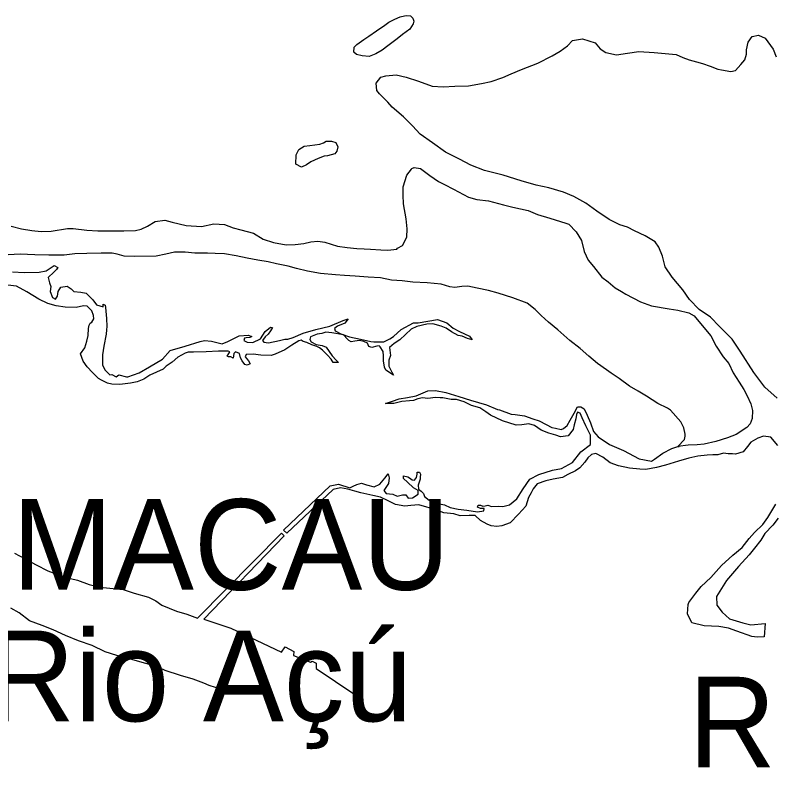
# Model space of a CAD drawing. Extents: x 662444 to 1640468, y 7452018 to 9606170.
# Drawn here: x 1427744 to 1433490, y 9427571 to 9433484 of the extents above; entities that cross this region are included whole.
import ezdxf

# ---------------------------------------------------------------- set-up
doc = ezdxf.new("R2010")
doc.units = 0
doc.layers.add('Level 1', color=7, linetype='Continuous')
doc.layers.add('Level 3', color=7, linetype='Continuous')

msp = doc.modelspace()

# ---------------------------------------------------------------- linework, layer by layer
at = {"layer": 'Level 1'}
for points in [[(1430678.3, 9433341.9), (1430636.3, 9433307.8), (1430565.1, 9433254), (1430523.2, 9433222.1), (1430475.8, 9433194.8), (1430425.1, 9433174.2), (1430372.5, 9433180.5), (1430328.9, 9433188.9), (1430307.9, 9433208.2), (1430311.7, 9433245), (1430332.2, 9433265.9), (1430385.3, 9433303.2), (1430421.5, 9433328.5), (1430481.4, 9433370.1), (1430542.4, 9433410.7), (1430574.1, 9433434.9), (1430619.2, 9433456.6), (1430659.8, 9433474), (1430692.4, 9433482.5), (1430710.4, 9433484.5), (1430738.4, 9433483), (1430756.1, 9433466), (1430762.5, 9433441.4), (1430758.8, 9433421.3), (1430732.6, 9433382.5), (1430678.3, 9433341.9)], [(1433519.7, 9430583.9), (1433425.5, 9430667.8), (1433340.7, 9430778.4), (1433238.6, 9430940.7), (1433177, 9431030.9), (1433081.9, 9431126), (1433013.4, 9431197.3), (1432927.9, 9431255.4), (1432852.7, 9431331.3), (1432804.3, 9431404.5), (1432722.7, 9431501.7), (1432668.8, 9431580.6), (1432648.6, 9431660.2), (1432621.5, 9431729.8), (1432592.8, 9431768.2), (1432518.4, 9431815), (1432437.1, 9431852.9), (1432382.5, 9431880.5), (1432325.6, 9431899.1), (1432245.5, 9431939.2), (1432151, 9432000.8), (1432067.8, 9432063.4), (1431977.7, 9432111.5), (1431897.4, 9432144.9), (1431788, 9432177.6), (1431690.8, 9432197.9), (1431577, 9432230.7), (1431442, 9432273.8), (1431299, 9432310.3), (1431196.4, 9432349.6), (1431108.5, 9432396.6), (1431003.9, 9432449.3), (1430904, 9432519.9), (1430810.7, 9432585.9), (1430753.3, 9432649.3), (1430685.8, 9432717.2), (1430598.2, 9432789.8), (1430566.2, 9432827.1), (1430502.1, 9432891.6), (1430483.4, 9432916.5), (1430478.5, 9432972.4), (1430513.8, 9433017.7), (1430552, 9433027.3), (1430628.3, 9433034.1), (1430706.5, 9433018.6), (1430798, 9432987.2), (1430902.8, 9432949), (1430984.6, 9432943.5), (1431074.3, 9432950.1), (1431177.4, 9432951), (1431276.2, 9432969.8), (1431349.3, 9432985.6), (1431439.3, 9433015.8), (1431502.4, 9433044), (1431579, 9433075.4), (1431704, 9433124.1), (1431811.2, 9433179.7), (1431872.2, 9433215.7), (1431929.8, 9433256.3), (1431967.3, 9433296.1), (1432042.6, 9433308.5), (1432138.5, 9433277.1), (1432177.2, 9433233), (1432220.5, 9433204.5), (1432299.8, 9433187.8), (1432384, 9433199), (1432470.5, 9433212.4), (1432585.8, 9433205.3), (1432753.7, 9433188.6), (1432802.7, 9433165.6), (1432851.7, 9433148.2), (1432907.6, 9433134.1), (1432951.1, 9433122.3), (1433010.2, 9433101.4), (1433068.2, 9433079.5), (1433096.2, 9433073.5), (1433167.7, 9433061.4), (1433202.5, 9433067.6), (1433243.5, 9433114), (1433274.2, 9433148.3), (1433284.9, 9433192.8), (1433285.3, 9433225.3), (1433299.5, 9433283.2), (1433328, 9433325.3), (1433376.4, 9433335.8), (1433427.6, 9433313.9), (1433487, 9433230.4), (1433510.9, 9433172)], [(1430108.3, 9432421.9), (1430083.6, 9432417.7), (1430038.6, 9432401.6), (1429982.2, 9432376.6), (1429948.3, 9432353.6), (1429911.1, 9432336.2), (1429868.8, 9432358), (1429872, 9432428.3), (1429891.5, 9432468.3), (1429932.2, 9432493.5), (1429976, 9432500.7), (1430050, 9432508.7), (1430078.2, 9432520.6), (1430099.6, 9432531.5), (1430138.9, 9432532.1), (1430171.2, 9432521.6), (1430187.6, 9432490.1), (1430180.5, 9432456.7), (1430163.4, 9432436.8), (1430108.3, 9432421.9)], [(1427710.4, 9431887.7), (1427788.6, 9431868.8), (1427865.7, 9431854.4), (1427937.3, 9431846.8), (1428013.5, 9431849.1), (1428135.9, 9431869.9), (1428180.7, 9431870.4), (1428282.5, 9431856.8), (1428366.5, 9431851.2), (1428470.7, 9431852.1), (1428563.7, 9431852), (1428653.3, 9431855.3), (1428694.9, 9431866), (1428743.4, 9431886.6), (1428802.1, 9431922.7), (1428876.2, 9431932.9), (1428932, 9431918.7), (1429037, 9431892.8), (1429152.3, 9431884.6), (1429246.7, 9431904.6), (1429327.3, 9431901.3), (1429394.2, 9431875.9), (1429452.2, 9431859.5), (1429548.3, 9431834.7), (1429620.5, 9431790.2), (1429699.7, 9431763.5), (1429795.9, 9431746.6), (1429863.1, 9431748), (1429929.3, 9431757.2), (1429983.3, 9431769.9), (1430036, 9431774.8), (1430088.6, 9431767.4), (1430183.4, 9431734.9), (1430257.2, 9431727.2), (1430330, 9431719.5), (1430387.1, 9431715.4), (1430434.1, 9431712.6), (1430513.6, 9431709.3), (1430566.2, 9431706.4), (1430635.7, 9431712.2), (1430640.3, 9431720), (1430676.5, 9431741.8), (1430709.8, 9431804), (1430712.8, 9431867.6), (1430706, 9431942.6), (1430686.2, 9432056.8), (1430682.5, 9432122.8), (1430683.4, 9432186.5), (1430711.4, 9432275.5), (1430746.7, 9432319.7), (1430749, 9432324.2), (1430764.8, 9432332.9), (1430814, 9432324.4), (1430883.9, 9432272.1), (1430950.6, 9432227.7)], [(1430950.6, 9432227.7), (1430995.1, 9432202.5), (1431064.1, 9432168.1), (1431178.7, 9432108.5), (1431241.2, 9432090.9), (1431330.7, 9432079.7), (1431443.5, 9432050.3), (1431515, 9432032.6), (1431631.2, 9432007.6), (1431701.4, 9431976.5), (1431794, 9431948.5), (1431916.8, 9431910), (1431939.1, 9431903), (1431993.2, 9431845.3), (1432035, 9431780), (1432055.2, 9431695.9), (1432084.6, 9431630.7), (1432126.5, 9431582.1), (1432189.3, 9431500.8), (1432235.9, 9431464.5), (1432291.3, 9431419), (1432336.9, 9431391.6), (1432371.4, 9431371.1), (1432482.7, 9431313.7), (1432566.3, 9431284.7), (1432700.5, 9431260.6), (1432766.4, 9431249.7), (1432849.1, 9431229.6), (1432890.3, 9431206.7), (1432949.8, 9431135.5), (1433016, 9431055.3), (1433055.3, 9430977.7), (1433108.1, 9430897.7), (1433151.1, 9430846.8), (1433184.9, 9430776), (1433231, 9430705), (1433266.2, 9430648.7), (1433290.2, 9430602.5), (1433319.6, 9430540.7), (1433331.3, 9430489.1), (1433328.3, 9430430), (1433313.2, 9430388.8), (1433288.2, 9430362.3), (1433207.9, 9430307.5), (1433141.5, 9430282.7), (1433052.6, 9430254.8), (1432966, 9430234.7), (1432911.1, 9430228.7), (1432844.9, 9430226.2), (1432765.2, 9430217.2), (1432774.2, 9430216)], [(1431622, 9431303.8), (1431513.9, 9431344.3), (1431402.3, 9431379.3), (1431329.7, 9431400.3), (1431244.8, 9431418.2), (1431172.1, 9431432.6), (1431126.2, 9431430.9), (1431074.5, 9431422.6), (1431035.4, 9431427.6), (1430969.6, 9431448.6), (1430865.5, 9431457.8), (1430755.8, 9431463.7), (1430675.2, 9431473.7), (1430593.5, 9431478.1), (1430509.7, 9431494.8), (1430417.9, 9431501.6), (1430319.3, 9431507.4), (1430238.8, 9431512.9), (1430168.2, 9431519.4), (1430056.3, 9431529.8), (1429957.9, 9431545.6), (1429874.2, 9431565.7), (1429809.4, 9431584.4), (1429722.3, 9431601.2), (1429658.6, 9431617.7), (1429579.2, 9431628.8), (1429498.8, 9431645.4), (1429416.1, 9431662.2), (1429327.8, 9431677.8), (1429257.2, 9431681), (1429197.8, 9431681.8), (1429103.7, 9431683), (1429028.8, 9431690.7), (1428948.1, 9431689.5), (1428881.8, 9431675.8), (1428809.9, 9431661.1), (1428645.2, 9431656.6), (1428566.8, 9431660.9), (1428514.3, 9431676.1), (1428476.3, 9431683.3), (1428460.6, 9431683.5), (1428391.2, 9431682.2), (1428284.7, 9431680.2), (1428193.9, 9431679.2), (1428110.9, 9431666.9), (1427994.4, 9431668.4), (1427889.1, 9431670.9), (1427779.3, 9431675.6), (1427686.3, 9431671.3)], [(1427720.5, 9431542.3), (1427807.8, 9431535.6), (1427921, 9431538.6), (1427974.9, 9431550.2), (1428034.8, 9431589.6), (1428063.7, 9431573.6), (1428053.4, 9431558.1), (1428034.1, 9431539.4), (1427989.9, 9431497.5), (1427999.5, 9431457.1), (1428010.3, 9431430.2), (1428005.4, 9431393.4), (1428023.8, 9431346.2), (1428046, 9431334.7), (1428060.9, 9431358), (1428067, 9431392.6), (1428086.4, 9431424.7), (1428133.6, 9431433.1), (1428165.8, 9431413.6), (1428184.6, 9431393.3), (1428238.3, 9431388.1), (1428279.7, 9431379.7), (1428328.3, 9431330), (1428358.1, 9431291.6), (1428407.1, 9431275.3), (1428408.5, 9431296.5), (1428423, 9431288.5), (1428425, 9431270.6), (1428431.8, 9431187.8), (1428434.4, 9431127.5), (1428431.8, 9431101.8), (1428429.1, 9431068.3), (1428413.4, 9430978), (1428402.4, 9430912.2), (1428401.4, 9430835.1), (1428420, 9430799.2)], [(1430259.3, 9431029.9), (1430229.5, 9431064.9), (1430142.3, 9431079.5), (1430096.5, 9431084.6), (1430066.1, 9431072.7), (1430030.2, 9431069.8), (1429979.5, 9431049.2), (1429973.6, 9431028.1), (1429984.6, 9431011.2), (1430022.4, 9430990.6), (1430067.1, 9430983.3), (1430099.5, 9430970.5), (1430120.3, 9430937.9), (1430143.4, 9430904.1), (1430173.3, 9430872.4), (1430190.9, 9430853.2), (1430150.6, 9430853.7), (1430136.4, 9430879.6), (1430108.8, 9430910.1), (1430071.2, 9430947.5), (1430047.8, 9430964.5), (1430026.7, 9430976), (1429988.8, 9430987.6), (1429953.1, 9431004.9), (1429924.1, 9431014.2), (1429909.7, 9431024.4), (1429890.6, 9431018), (1429838.6, 9430986.2), (1429784.4, 9430950.1), (1429712.2, 9430917.5), (1429681.8, 9430906.7), (1429602.3, 9430908.9), (1429544.1, 9430916.3), (1429491.5, 9430915.9), (1429485.6, 9430895.9), (1429509.9, 9430865.4), (1429523, 9430842.9), (1429499.4, 9430833.1), (1429482.6, 9430837.8), (1429462.8, 9430866), (1429448.5, 9430888.5), (1429442.3, 9430923.3), (1429412.2, 9430933.7), (1429398.6, 9430922.7), (1429392.5, 9430885.9), (1429374.7, 9430897.3), (1429357.9, 9430896.4), (1429349, 9430902.1), (1429359.3, 9430921), (1429368.5, 9430935.4), (1429355.1, 9430941.1), (1429329.4, 9430940.4), (1429283.4, 9430939.9), (1429188.1, 9430934.4), (1429092.8, 9430931.2), (1429052.5, 9430931.7), (1429028.9, 9430925.3), (1428974.7, 9430894.7), (1428930.5, 9430857.3), (1428886.4, 9430825.5), (1428862.6, 9430802.3), (1428761.2, 9430757.8), (1428716, 9430728.3), (1428664.2, 9430707.7), (1428613.6, 9430697.2), (1428533.9, 9430688.2), (1428473.5, 9430690.1), (1428441.1, 9430697.2), (1428395.4, 9430719), (1428372.1, 9430733.8), (1428327.8, 9430778), (1428286.9, 9430819.9), (1428255, 9430865), (1428235.6, 9430920), (1428267.5, 9430965.4), (1428283.9, 9431015.5), (1428293.4, 9431060), (1428295.2, 9431111.4), (1428302.3, 9431135.9), (1428309.2, 9431151.4), (1428321.6, 9431160.2), (1428337.6, 9431185.7), (1428333.5, 9431211.4), (1428320.5, 9431245.1), (1428285.1, 9431280.2), (1428259.3, 9431282.8), (1428202.1, 9431271.3), (1428119.2, 9431274.6), (1428051, 9431283.3), (1427987.3, 9431300.9), (1427919.4, 9431334.2), (1427829.4, 9431389), (1427749.3, 9431433.6), (1427685.5, 9431441.1)], [(1432086.7, 9430333.4), (1432067, 9430375), (1432039.8, 9430433.4), (1432025.7, 9430470.5), (1432005.6, 9430478.6), (1431997.5, 9430459.7), (1431992.6, 9430427.3), (1431978.6, 9430381.7), (1431972.5, 9430344.9), (1431933.8, 9430297.4), (1431876.6, 9430291.4), (1431840.8, 9430301.9), (1431786.2, 9430319.4), (1431729.3, 9430341.4), (1431679.4, 9430375.6), (1431634.7, 9430389.6), (1431582, 9430382.4), (1431539.3, 9430378.5), (1431436.7, 9430411.2), (1431345.4, 9430453.7), (1431308.7, 9430481), (1431263.2, 9430509.5), (1431201.8, 9430528.2), (1431143.9, 9430554.7), (1431087, 9430572.2), (1431071.3, 9430572.4), (1431045.5, 9430572.7), (1430984.1, 9430585.8), (1430963.9, 9430586.1), (1430927, 9430588.8), (1430869.7, 9430581.7), (1430828.3, 9430586.7), (1430793.5, 9430578.2), (1430762, 9430566.4), (1430729.4, 9430563.4), (1430672.2, 9430558.6), (1430611.5, 9430542.6), (1430548.8, 9430543.4), (1430601.7, 9430561.7), (1430652.3, 9430579), (1430716.3, 9430588.2), (1430780.3, 9430600.8), (1430869.3, 9430638.7), (1430927.6, 9430641.3), (1431007, 9430626.8), (1431105.2, 9430595.4), (1431192.2, 9430567.4), (1431313.9, 9430533.4), (1431398.6, 9430496.6), (1431413.1, 9430495.3), (1431501.2, 9430461.7), (1431532.5, 9430459), (1431601.9, 9430450.3), (1431666.6, 9430426), (1431713.4, 9430410.9), (1431768, 9430384.5), (1431810.2, 9430360.4), (1431837.1, 9430355.6), (1431880.7, 9430347.2), (1431898.7, 9430352.6), (1431925.9, 9430376.8), (1431947.7, 9430415.6), (1431979.7, 9430470), (1432003.9, 9430518.8), (1432030.8, 9430517.3), (1432055.3, 9430503.6), (1432077, 9430454.2), (1432102, 9430395.7), (1432124.7, 9430331.7), (1432160, 9430291.1), (1432247.8, 9430232.9), (1432352.5, 9430185.7), (1432472.7, 9430123.8), (1432565.5, 9430105.8), (1432589.2, 9430120.1), (1432652.5, 9430166.2), (1432720.2, 9430202.1), (1432765.2, 9430217.2), (1432815.2, 9430269.1), (1432821.2, 9430295.8), (1432821.4, 9430310.3), (1432811.9, 9430359.6), (1432787.9, 9430404.6), (1432709.5, 9430492.8), (1432687.2, 9430506.5), (1432612.7, 9430543.2), (1432527.1, 9430598), (1432464.9, 9430636.8), (1432399.2, 9430674.5), (1432320.5, 9430733.7), (1432259.4, 9430773.6), (1432223.8, 9430798.7), (1432157.2, 9430846.4), (1432089.6, 9430903.2), (1432025.4, 9430961), (1431946.6, 9431020.2), (1431854.7, 9431100.7), (1431784.9, 9431160.8), (1431728.3, 9431209.6), (1431684.1, 9431256), (1431622, 9431303.8)], [(1428420, 9430799.2), (1428457.6, 9430760.7), (1428474.4, 9430763.8), (1428505.5, 9430744.4), (1428527, 9430759.8), (1428585.1, 9430745.6), (1428594.1, 9430745.5), (1428679.6, 9430774.5), (1428759.7, 9430820.4), (1428856.9, 9430879.5), (1428916, 9430945.8), (1429028.4, 9430977.8), (1429144.3, 9431013.2), (1429175.8, 9431020.6), (1429229.5, 9431015.4), (1429309.9, 9430995.4), (1429353.8, 9431013.8), (1429439.5, 9431056.3), (1429508, 9431062.1), (1429534.7, 9431050.5), (1429518.9, 9431042.9), (1429490.9, 9431042.2), (1429479.7, 9431039), (1429473.8, 9431020), (1429498.3, 9431008.6), (1429542, 9431005.8), (1429600.6, 9431034), (1429636, 9431089.5), (1429676.8, 9431122.4), (1429692.5, 9431120), (1429676.4, 9431093.4), (1429659.3, 9431069), (1429636.6, 9431048.1), (1429615, 9431020.4), (1429624.9, 9431008), (1429661.8, 9431004.2), (1429743.8, 9431021), (1429784.3, 9431031.6), (1429807.8, 9431031.3), (1429847.2, 9431043.1), (1429924.9, 9431076.7), (1430019.4, 9431104.6), (1430126.2, 9431128.9), (1430227.6, 9431172.2), (1430264.7, 9431186.3), (1430239.6, 9431152), (1430184.5, 9431130.3), (1430161.8, 9431111.6), (1430166.1, 9431094.8), (1430210.6, 9431071.9), (1430275.3, 9431048.7), (1430360.2, 9431032), (1430438.4, 9431014.2), (1430459.7, 9431010.5), (1430534.7, 9431011.8), (1430582.1, 9431033.5), (1430608.1, 9431051.1), (1430667, 9431103.9), (1430760.7, 9431155.2), (1430795.4, 9431155.9), (1430942.5, 9431180.8), (1431013.9, 9431155.3), (1431060.5, 9431115.6), (1431109.4, 9431089.2), (1431186.3, 9431054.7), (1431206.1, 9431025.4), (1431171.5, 9431037), (1431129.1, 9431053.2), (1431098.9, 9431058.1), (1431048.9, 9431085.5), (1431008.9, 9431115.1), (1430971, 9431129), (1430906.2, 9431147.7), (1430861.4, 9431145), (1430785, 9431127), (1430743.2, 9431106.3), (1430658.2, 9431025.8), (1430613, 9430997.4), (1430579, 9430967.6), (1430586, 9430907.2), (1430573.2, 9430872.7), (1430572.6, 9430825.8), (1430597.8, 9430779.7), (1430609.8, 9430757.2), (1430552.1, 9430795.9), (1430541.2, 9430818.4), (1430534, 9430867.7), (1430534.5, 9430905.7), (1430531.5, 9430938.1), (1430508.4, 9430971.9), (1430499.6, 9430979.9), (1430483.9, 9430977.8), (1430444.5, 9430967.2), (1430422.2, 9430976.4), (1430412.4, 9431000), (1430383.5, 9431013.8), (1430352.2, 9431022), (1430316.3, 9431015.8), (1430289.3, 9431011.6), (1430270.4, 9431019.7), (1430259.3, 9431029.9)], [(1431430.7, 9429614.5), (1431392.6, 9429610.6), (1431350.1, 9429615.6), (1431318.9, 9429628.3), (1431267.7, 9429654.7), (1431227.8, 9429693.2), (1431181.9, 9429692.7), (1431115.8, 9429692.4), (1431065.5, 9429705.4), (1430990.6, 9429715.3), (1430932.6, 9429736.1), (1430861.2, 9429758.3), (1430802, 9429775.8), (1430740.3, 9429768.8), (1430695.4, 9429763.8), (1430625, 9429777), (1430569.4, 9429805.7), (1430510.3, 9429832.2), (1430453.4, 9429845.2), (1430360.7, 9429866.5), (1430316, 9429878.3), (1430263.5, 9429892.4), (1430207.7, 9429904.3), (1430152.6, 9429891.6), (1429799.8, 9429558.8), (1429775.4, 9429581.4), (1430129.4, 9429919.8), (1430192.3, 9429931.3), (1430278.2, 9429904.5), (1430303, 9429915.3), (1430332.3, 9429928.4), (1430366.1, 9429938), (1430404, 9429927.4), (1430462.1, 9429911), (1430506, 9429930.6), (1430543.6, 9429978.1), (1430569.8, 9430009.1), (1430577.3, 9429978.8), (1430572.2, 9429936.4), (1430535.7, 9429883.2), (1430553.3, 9429859.5), (1430603.6, 9429854.4), (1430637.1, 9429840.6), (1430678.6, 9429850.1), (1430702.2, 9429849.8), (1430720.9, 9429826.1), (1430754.5, 9429826.7), (1430795.2, 9429855.3), (1430796.7, 9429884.3), (1430761.1, 9429902.6), (1430715.7, 9429945.7), (1430685.9, 9429974), (1430686.1, 9429995.2), (1430718.5, 9429985.9), (1430729.6, 9429979), (1430750.7, 9429963.1), (1430767.5, 9429960.6), (1430783.4, 9429981.7), (1430788.3, 9430007.3), (1430788.5, 9430021.8), (1430806.4, 9430022.7), (1430812.9, 9430007), (1430812.6, 9429984.6), (1430811.3, 9429969), (1430804.3, 9429945.6), (1430796.1, 9429923.4), (1430799.1, 9429893.2), (1430819.1, 9429878.4), (1430835.7, 9429861.4), (1430844.3, 9429837.9), (1430880.9, 9429810.6), (1430935.5, 9429787.5), (1430995.9, 9429775.5), (1431038.2, 9429753.8), (1431099.6, 9429740.7), (1431164.5, 9429734.2), (1431246.1, 9429722), (1431293.3, 9429730.3), (1431296.9, 9429747), (1431268.9, 9429747.4), (1431245.5, 9429757.8), (1431250.2, 9429773.3), (1431268.1, 9429773.1), (1431287, 9429765), (1431305, 9429765.9), (1431325.2, 9429772.3), (1431353.1, 9429763), (1431404.7, 9429763.5), (1431437.2, 9429763.1), (1431488.8, 9429773.5), (1431545.5, 9429820.9), (1431591.3, 9429895.1), (1431642.6, 9429968.2), (1431711.5, 9430004.2), (1431813.9, 9430037.5), (1431882.4, 9430050), (1431967, 9430096.9), (1432030.8, 9430176.5), (1432102.1, 9430232.6), (1432103, 9430303), (1432086.7, 9430333.4)], [(1433523.9, 9430225.1), (1433471, 9430287.3), (1433415, 9430294.7), (1433372.3, 9430279.7), (1433318.1, 9430249.1), (1433293, 9430218.1), (1433261.1, 9430176.1), (1433203.7, 9430160.1), (1433180.2, 9430160.4), (1433147.7, 9430161.9), (1433110.8, 9430165.7), (1433069.2, 9430154), (1433031.1, 9430154.5), (1432988.5, 9430151.7), (1432917.8, 9430142.6), (1432848.1, 9430127.8), (1432770.5, 9430105.4), (1432672.6, 9430074.3), (1432604.1, 9430058.4), (1432522.1, 9430043.8), (1432477.3, 9430044.4), (1432397.8, 9430052.2), (1432315.1, 9430070), (1432251.6, 9430094.3), (1432197.2, 9430135.3), (1432142.7, 9430162.8), (1432111.2, 9430155.4), (1432084, 9430130), (1432060, 9430097.9), (1432022.5, 9430054.8), (1431988.6, 9430031.8), (1431932.2, 9430003.5), (1431890.4, 9429981.7), (1431819.7, 9429969.2), (1431764.6, 9429956.5), (1431698.2, 9429933.9), (1431667.5, 9429896.4), (1431653.6, 9429865.3), (1431634.1, 9429830.9), (1431612, 9429764.1), (1431557.4, 9429703.4), (1431492.7, 9429639.4), (1431430.7, 9429614.5)], [(1433525.7, 9429674.2), (1433486.9, 9429621.1), (1433424.4, 9429558.2), (1433394.6, 9429507.2), (1433345.6, 9429446.4), (1433306.9, 9429395.5), (1433225, 9429306), (1433134, 9429202.2), (1433059.6, 9429080.3), (1433060.9, 9429013.2), (1433101.7, 9428961.3), (1433158.2, 9428911.3), (1433257.5, 9428879.9), (1433317.8, 9428864.6), (1433426.6, 9428875.4), (1433420.8, 9428773.8), (1433365.9, 9428772.3), (1433326.8, 9428777.3), (1433213, 9428816.8), (1433150.5, 9428838.8), (1433075.6, 9428852.1), (1432965.9, 9428858), (1432870.9, 9428879.4), (1432838.3, 9428949.1), (1432843.7, 9429019.4), (1432848.3, 9429035), (1432863.1, 9429053.8), (1432903, 9429104.7), (1432942.9, 9429156.7), (1433014.4, 9429223.9), (1433095.2, 9429315.6), (1433182.5, 9429393.8), (1433252.7, 9429452.1), (1433306.2, 9429519.5), (1433346.1, 9429564.8), (1433410.7, 9429626.6), (1433448.4, 9429678.6), (1433508, 9429779.5)], [(1427736.3, 9429407), (1427809.8, 9429368), (1427898.8, 9429321), (1427988.9, 9429275.2), (1428117.1, 9429225.5), (1428212.1, 9429204.1), (1428302.4, 9429169.4), (1428381.7, 9429150.5), (1428458.9, 9429143.9), (1428559.6, 9429132.5), (1428642.1, 9429104.6), (1428751.5, 9429075.3), (1428806, 9429046.6), (1428851.6, 9429013.6), (1428963, 9428967.5), (1429042.2, 9428945.2), (1429123.6, 9428916.2), (1429760.6, 9429559.3), (1429779.4, 9429538.9), (1429170.6, 9428908.9), (1429375.8, 9428840.3), (1429761.1, 9428656.5), (1429787.4, 9428697.5), (1429854.2, 9428661.9), (1429850.4, 9428631.8), (1429978.6, 9428581), (1429993.3, 9428589.7), (1430022.2, 9428573.7), (1430021.7, 9428533.5), (1430316, 9428337.4)], [(1429319.2, 9428363.9), (1429260.2, 9428389.3), (1429211.1, 9428405.6), (1429171, 9428422.8), (1429089.6, 9428453), (1428993.6, 9428481), (1428878.7, 9428518.3), (1428807.4, 9428550.5), (1428720.3, 9428574), (1428606.5, 9428607.9), (1428510.4, 9428631.5), (1428423.4, 9428659.4), (1428324.4, 9428708.8), (1428219.5, 9428742.6), (1428122.5, 9428782.9), (1428029, 9428826.6), (1427945.4, 9428860.1), (1427849.5, 9428894.9), (1427770.8, 9428956.2), (1427707.4, 9428990.6)]]:
    msp.add_lwpolyline(points, dxfattribs=at)

# ---------------------------------------------------------------- texts
at = {"layer": 'Level 3'}
for s, height, p in [('MACAU', 687.6, (1427716.9, 9429130.3)), ('Rio Açú', 687.61, (1427529.3, 9428133.7)), ('Rio Conceição', 687.729, (1432844.8, 9427783.3))]:
    msp.add_text(s, height=height, dxfattribs=at).set_placement(p)

doc.saveas('drawing.dxf')
